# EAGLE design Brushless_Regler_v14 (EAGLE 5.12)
BENENNUNG: BL-Regler v14; DATUM: 27.01.2012; PROJEKT: Quadrokopter v1; SEITE: 1; ZEICHNER: Urban B.
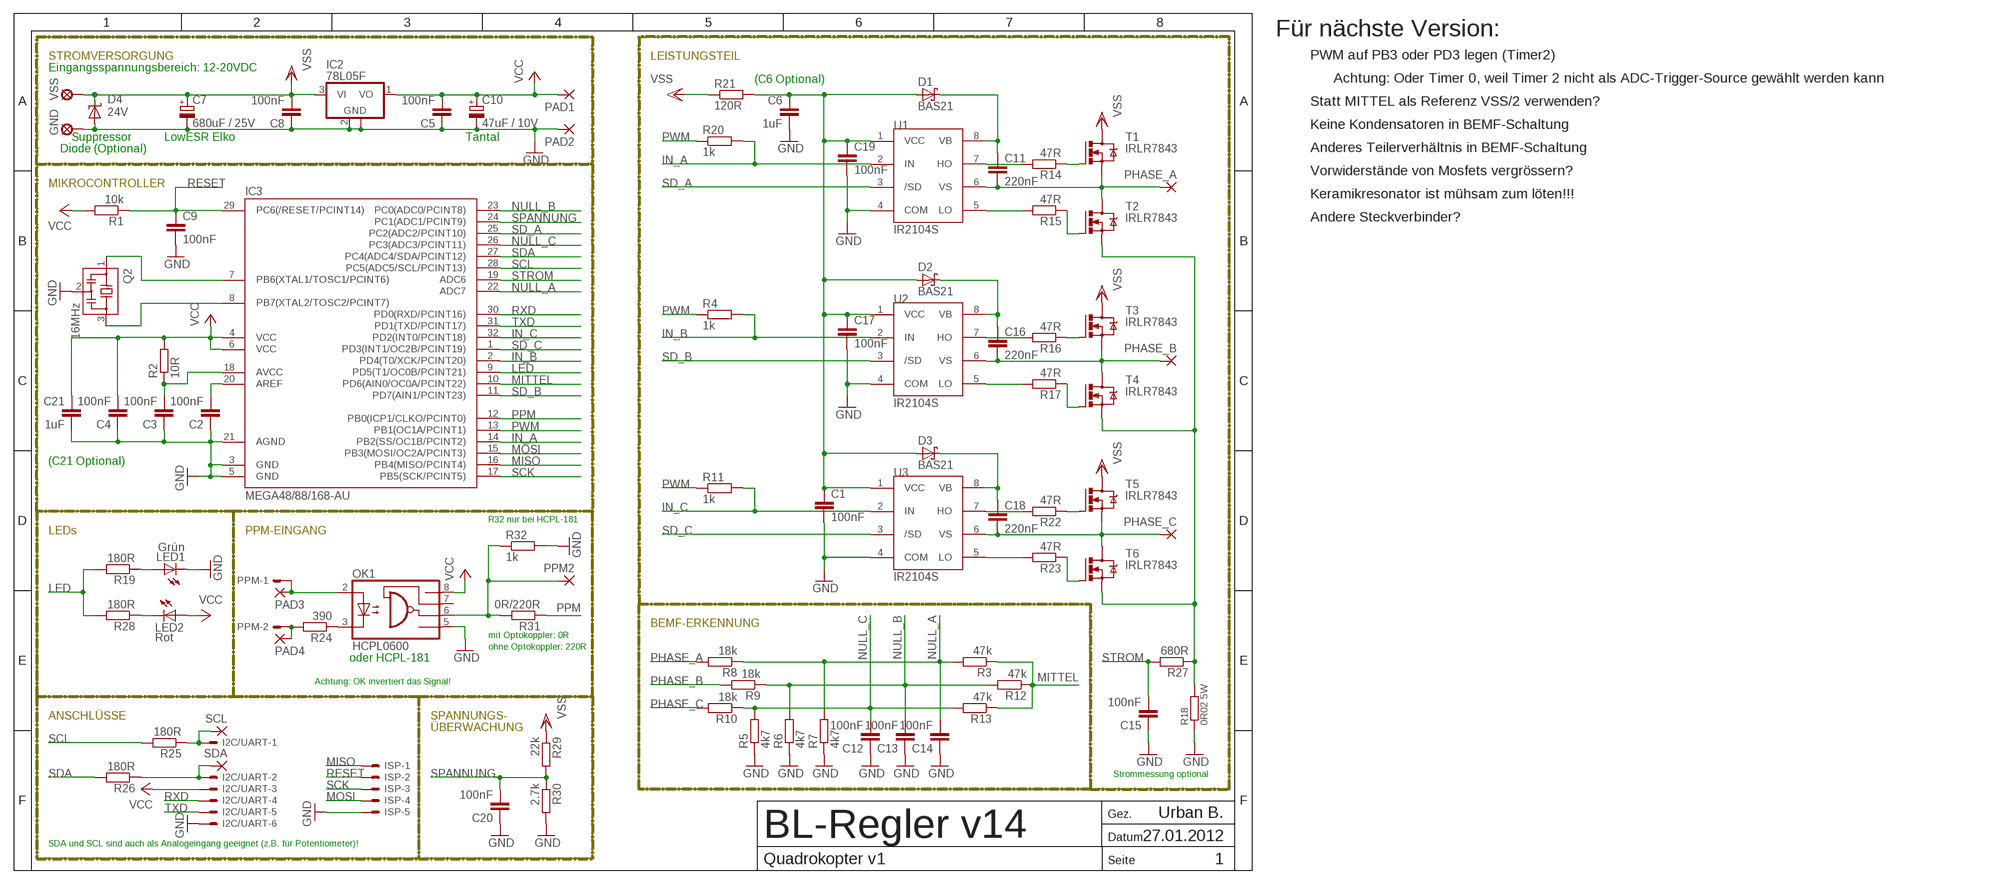
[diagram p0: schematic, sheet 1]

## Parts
C1  100nF  C-EUC0603  [C0603]
C2  100nF  C-EUC0603  [C0603]
C3  100nF  C-EUC0603  [C0603]
C4  100nF  C-EUC0603  [C0603]
C5  100nF  C-EUC0603  [C0603]
C6  1uF  C-EUC0805  [C0805]
C7  680uF / 25V  CPOL-EUE5-10.5  [E5-10,5]
C8  100nF  C-EUC0603  [C0603]
C9  100nF  C-EUC0603  [C0603]
C10  47uF / 10V  CPOL-EUB/3528-21R  [B/3528-21R]
C11  220nF  C-EUC0603  [C0603]
C12  100nF  C-EUC0603  [C0603]
C13  100nF  C-EUC0603  [C0603]
C14  100nF  C-EUC0603  [C0603]
C15  100nF  C-EUC0603  [C0603]
C16  220nF  C-EUC0603  [C0603]
C17  100nF  C-EUC0603  [C0603]
C18  220nF  C-EUC0603  [C0603]
C19  100nF  C-EUC0603  [C0603]
C20  100nF  C-EUC0603  [C0603]
C21  1uF  C-EUC0805  [C0805]
D1  BAS21  BAS40  [SOT23]
D2  BAS21  BAS40  [SOT23]
D3  BAS21  BAS40  [SOT23]
D4  24V  SUPPRESSOR-SMBJ  [SMBJ]
GND  SE14  [SE14]
I2C/UART  53261-06  [53261-06]
IC2  78L05F  [SOT89]
IC3  MEGA48/88/168-AU  [TQFP32-08]
ISP  53261-05  [53261-05]
LED1  Grün  LEDCHIP-LED0805  [CHIP-LED0805]
LED2  Rot  LEDCHIP-LED0805  [CHIP-LED0805]
OK1  HCPL0600  [SOIC08]
PAD1  SMD2  [SMD1,27-2,54]
PAD2  SMD2  [SMD1,27-2,54]
PAD3  SMD2  [SMD1,27-2,54]
PAD4  SMD2  [SMD1,27-2,54]
PHASE_A  WIREPADSMD5-1,8  [5-1,8]
PHASE_B  WIREPADSMD5-1,8  [5-1,8]
PHASE_C  WIREPADSMD5-1,8  [5-1,8]
PPM  53398-02  [53398-02]
PPM2  SMD2  [SMD1,27-2,54]
Q2  16MHz  CSTCR6M00G53Z  [CSTCR6M]
R1  10k  R-EU_R0603  [R0603]
R2  10R  R-EU_R0603  [R0603]
R3  47k  R-EU_R0603  [R0603]
R4  1k  R-EU_R0603  [R0603]
R5  4k7  R-EU_R0603  [R0603]
R6  4k7  R-EU_R0603  [R0603]
R7  4k7  R-EU_R0603  [R0603]
R8  18k  R-EU_R0603  [R0603]
R9  18k  R-EU_R0603  [R0603]
R10  18k  R-EU_R0603  [R0603]
R11  1k  R-EU_R0603  [R0603]
R12  47k  R-EU_R0603  [R0603]
R13  47k  R-EU_R0603  [R0603]
R14  47R  R-EU_R0603  [R0603]
R15  47R  R-EU_R0603  [R0603]
R16  47R  R-EU_R0603  [R0603]
R17  47R  R-EU_R0603  [R0603]
R18  0R02 5W  SMT-WAV  [SMT-WAV]
R19  180R  R-EU_R0603  [R0603]
R20  1k  R-EU_R0603  [R0603]
R21  120R  R-EU_R0603  [R0603]
R22  47R  R-EU_R0603  [R0603]
R23  47R  R-EU_R0603  [R0603]
R24  390  R-EU_R0603  [R0603]
R25  180R  R-EU_R0603  [R0603]
R26  180R  R-EU_R0603  [R0603]
R27  680R  R-EU_R0603  [R0603]
R28  180R  R-EU_R0603  [R0603]
R29  22k  R-EU_R0603  [R0603]
R30  2.7k  R-EU_R0603  [R0603]
R31  0R/220R  R-EU_R0603  [R0603]
R32  1k  R-EU_R0603  [R0603]
SCL  SMD2  [SMD1,27-2,54]
SDA  SMD2  [SMD1,27-2,54]
T1  IRLR7843  IRFR1205  [DPACK]
T2  IRLR7843  IRFR1205  [DPACK]
T3  IRLR7843  IRFR1205  [DPACK]
T4  IRLR7843  IRFR1205  [DPACK]
T5  IRLR7843  IRFR1205  [DPACK]
T6  IRLR7843  IRFR1205  [DPACK]
U1  IR2104S  IR2104NEU  [SOIC8_V2]
U2  IR2104S  IR2104NEU  [SOIC8_V2]
U3  IR2104S  IR2104NEU  [SOIC8_V2]
VSS  SE14  [SE14]

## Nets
GND: C1.2 C2.1 C3.1 C4.1 C5.1 C6.2 C7.- C8.1 C9.2 C10.- C12.1 C13.1 C14.1 C15.1 C17.2 C19.2 C20.1 C21.2 D4.A GND.MP I2C/UART.6 IC2.2(GND) IC2.2@1(GND) IC3.3(GND) IC3.5(GND) IC3.21(AGND) ISP.5 LED1.C OK1.5(GND) PAD2.1(P) Q2.2 R5.1 R6.1 R7.1 R18.2 R30.2 R32.2 U1.4(COM) U2.4(COM) U3.4(COM)
IN_A: IC3.14(PB2(SS/OC1B/PCINT2)) R20.2 U1.2(IN)
IN_B: IC3.2(PD4(T0/XCK/PCINT20)) R4.2 U2.2(IN)
IN_C: IC3.32(PD2(INT0/PCINT18)) R11.2 U3.2(IN)
LED: IC3.9(PD5(T1/OC0B/PCINT21)) R19.2 R28.2
MISO: IC3.16(PB4(MISO/PCINT4)) ISP.1
MITTEL: IC3.10(PD6(AIN0/OC0A/PCINT22)) R3.1 R12.1 R13.1
MOSI: IC3.15(PB3(MOSI/OC2A/PCINT3)) ISP.4
N$1: C2.2 IC3.20(AREF)
N$2: C3.2 IC3.18(AVCC) R2.1
N$3: IC3.8(PB7(XTAL2/TOSC2/PCINT7)) Q2.3
N$4: IC3.7(PB6(XTAL1/TOSC1/PCINT6)) Q2.1
N$5: R15.1 T2.1(G)
N$6: R14.1 T1.1(G)
N$7: R17.1 T4.1(G)
N$8: R14.2 U1.7(HO)
N$9: R16.1 T3.1(G)
N$10: R16.2 U2.7(HO)
N$11: R15.2 U1.5(LO)
N$12: R17.2 U2.5(LO)
N$13: LED1.A R19.1
N$14: LED2.C R28.1
N$15: OK1.3(C) R24.1
N$16: OK1.2(A) PAD3.1(P) PPM.1
N$19: I2C/UART.2 R26.1 SDA.1(P)
N$20: I2C/UART.1 R25.1 SCL.1(P)
N$21: R23.1 T6.1(G)
N$22: R22.1 T5.1(G)
N$23: R22.2 U3.7(HO)
N$26: R23.2 U3.5(LO)
N$30: C11.1 D1.3(C) U1.8(VB)
N$36: PAD4.1(P) PPM.2 R24.2
N$50: OK1.6(VO) PPM2.1(P) R31.2 R32.1
NULL_A: C14.2 IC3.22(ADC7) R3.2 R7.2 R8.1
NULL_B: C13.2 IC3.23(PC0(ADC0/PCINT8)) R6.2 R9.1 R12.2
NULL_C: C12.2 IC3.26(PC3(ADC3/PCINT11)) R5.2 R10.1 R13.2
PHASE_A: C11.2 PHASE_A.1(P) R8.2 T1.3(S) T2.2(D) U1.6(VS)
PHASE_B: C16.2 PHASE_B.1(P) R9.2 T3.3(S) T4.2(D) U2.6(VS)
PHASE_C: C18.2 PHASE_C.1(P) R10.2 T5.3(S) T6.2(D) U3.6(VS)
PPM: IC3.12(PB0(ICP1/CLKO/PCINT0)) R31.1
PWM: IC3.13(PB1(OC1A/PCINT1)) R4.1 R11.1 R20.1
RESET: C9.1 IC3.29(PC6(/RESET/PCINT14)) ISP.2 R1.1
RXD: I2C/UART.4 IC3.30(PD0(RXD/PCINT16))
SCK: IC3.17(PB5(SCK/PCINT5)) ISP.3
SCL: IC3.28(PC5(ADC5/SCL/PCINT13)) R25.2
SD_A: IC3.25(PC2(ADC2/PCINT10)) U1.3(/SD)
SD_B: IC3.11(PD7(AIN1/PCINT23)) U2.3(/SD)
SD_C: IC3.1(PD3(INT1/OC2B/PCINT19)) U3.3(/SD)
SDA: IC3.27(PC4(ADC4/SDA/PCINT12)) R26.2
SENSE: R18.1 R27.1 T2.3(S) T4.3(S) T6.3(S)
SPANNUNG: C20.2 IC3.24(PC1(ADC1/PCINT9)) R29.2 R30.1
STROM: C15.2 IC3.19(ADC6) R27.2
TXD: I2C/UART.5 IC3.31(PD1(TXD/PCINT17))
VBB: C16.1 D2.3(C) U2.8(VB)
VBC: C18.1 D3.3(C) U3.8(VB)
VCC: C4.2 C5.2 C10.+ C21.1 I2C/UART.3 IC2.1(VO) IC3.4(VCC) IC3.6(VCC) LED2.A OK1.8(VCC) PAD1.1(P) R1.2 R2.2
VSS: C7.+ C8.2 D4.C IC2.3(VI) R21.1 R29.1 T1.2(D) T3.2(D) T5.2(D) VSS.MP
VSS2: C1.1 C6.1 C17.1 C19.1 D1.1(A) D2.1(A) D3.1(A) R21.2 U1.1(VCC) U2.1(VCC) U3.1(VCC)
Unconnected: OK1.7(VE)

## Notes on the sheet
- Für nächste Version:
- STROMVERSORGUNG | LEISTUNGSTEIL | PWM auf PB3 oder PD3 legen (Timer2)
- Eingangsspannungsbereich: 12-20VDC
- (C6 Optional) | Achtung: Oder Timer 0, weil Timer 2 nicht als ADC-Trigger-Source gewählt werden kann
- Statt MITTEL als Referenz VSS/2 verwenden?
- Keine Kondensatoren in BEMF-Schaltung
- Suppressor | LowESR Elko | Tantal
- Diode (Optional) | Anderes Teilerverhältnis in BEMF-Schaltung
- Vorwiderstände von Mosfets vergrössern?
- MIKROCONTROLLER
- Keramikresonator ist mühsam zum löten!!!
- Andere Steckverbinder?
- (C21 Optional)
- R32 nur bei HCPL-181
- LEDs | PPM-EINGANG
- BEMF-ERKENNUNG
- mit Optokoppler: 0R
- ohne Optokoppler: 220R
- oder HCPL-181
- Achtung: OK invertiert das Signal!
- ANSCHLÜSSE | SPANNUNGS-
- ÜBERWACHUNG
- Strommessung optional
- SDA und SCL sind auch als Analogeingang geeignet (z.B. für Potentiometer)!

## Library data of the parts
C1-C6 C8 C9 C11-C21 = resistor:C-EU: CAPACITOR, European symbol
C7 C10 = resistor:CPOL-EU: POLARIZED CAPACITOR, European symbol
D1-D3 = diode:BAS40: Silicon Schottky Diodes
D4 = diode:SUPPRESSOR-: Suppressor diode
GND VSS = solpad:SE14: SOLDER PAD
I2C/UART = con-molex:53?-06: CONNECTOR wire to board 1.25 mm (.049 inch) pitch header
IC2 = linear:78L*: POSITOIV-VOLTAGE REGULATORS Output up to 100 mA Source: http://focus.ti.com/lit/ds/symlink/ua78l05.pdf
IC3 = avr-6:MEGA48/88/168
ISP = con-molex:53?-05: CONNECTOR wire to board 1.25 mm (.049 inch) pitch header
LED1 LED2 = led:LED: LED
OK1 = optocoupler:HCPL0600: HEWLETT PACKARD OPTO COUPLER
PAD1-PAD4 PPM2 SCL SDA = wirepad:SMD2: SMD PAD
PHASE_A PHASE_B PHASE_C = wirepad:WIREPAD: Wire PAD connect wire on PCB
PPM = con-molex:53?-02: CONNECTOR
Q2 = murata-filter:CSTCR: Resonator Source: murata.co.jp
R1-R17 R19-R32 = resistor:R-EU_: RESISTOR, European symbol
R18 = isabellen:SMT-WAV
T1-T6 = irf-3:IRFR1205
U1-U3 = 0_ICs:IR2104

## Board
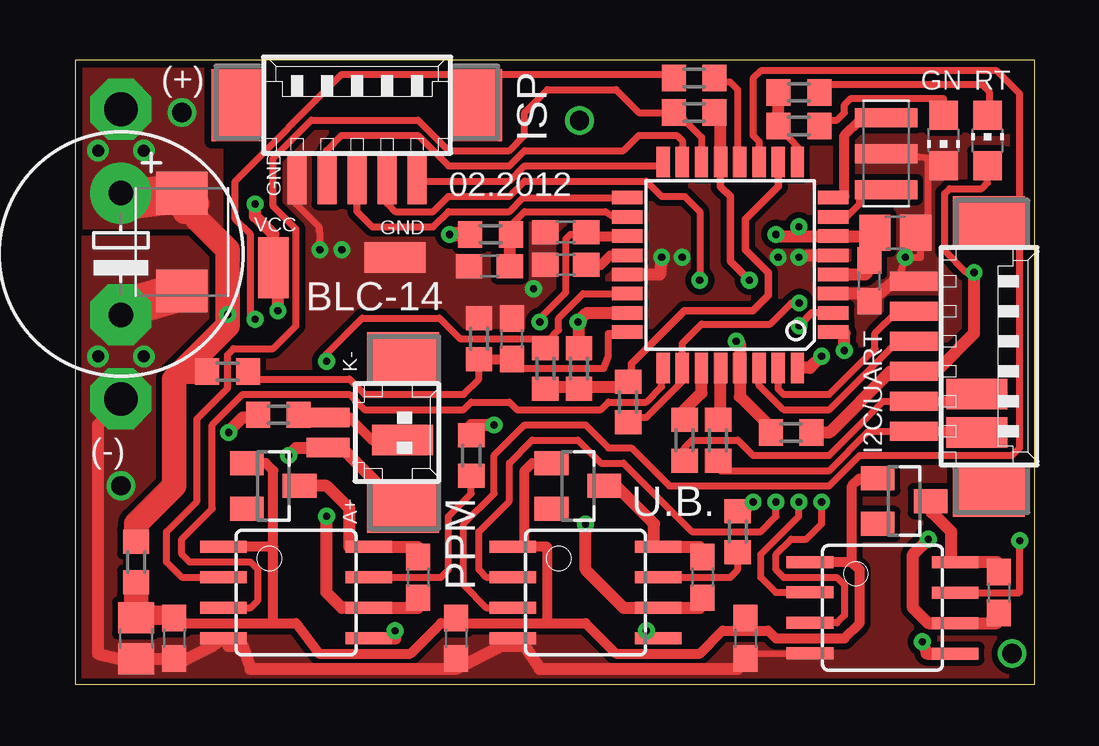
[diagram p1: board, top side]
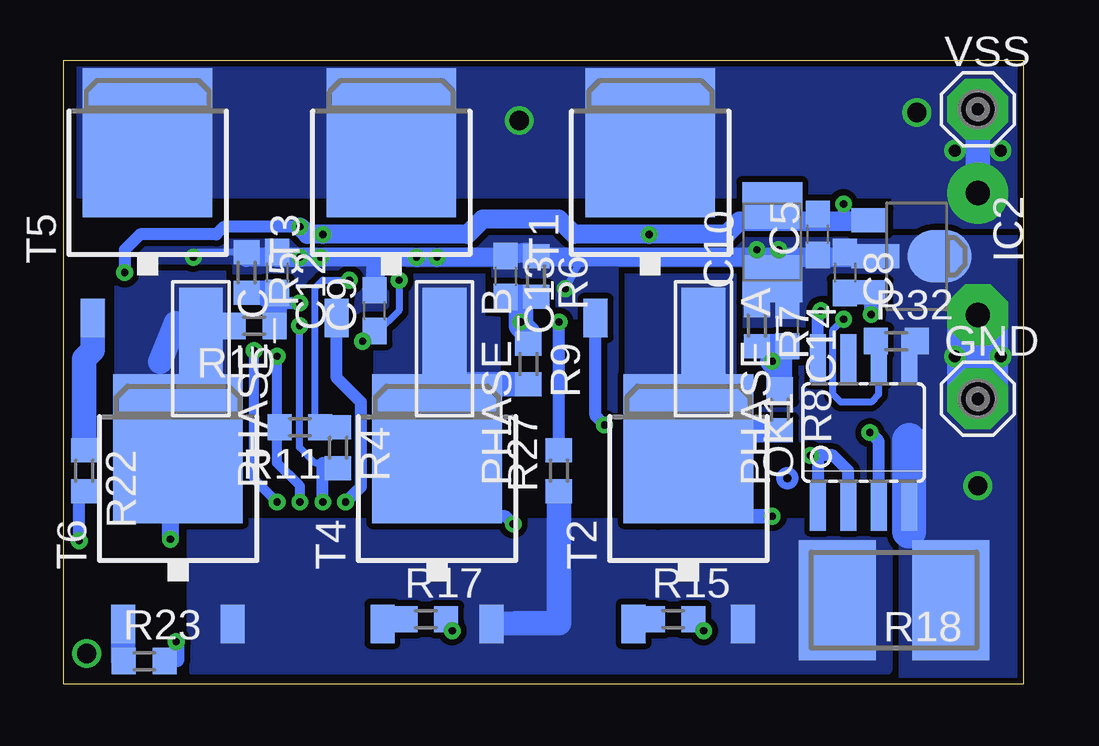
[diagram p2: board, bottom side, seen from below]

Size 40 x 26 mm. Coordinates in mm from the lower left corner, seen from the top.
Outline: 0,0 40,0 40,26 0,26 0,0
Copper layers (1*16): Top 0.035mm / dielectric 1.5mm / Bottom 0.035mm
Design rules "platinensammler_02": minimum track width 0.15mm, minimum drill 0.3mm, track to track 0.15mm, track to pad 0.15mm, pad to pad 0.15mm, via to via 0.15mm, smd to smd 0mil, copper to edge 0.2mm, drill to drill 0.2mm, minimum pad ring 0.2mm, minimum via ring 0.2mm, stop-mask expansion 4mil, vias tented up to drill 0.8mm, thermal gap 0.15mm

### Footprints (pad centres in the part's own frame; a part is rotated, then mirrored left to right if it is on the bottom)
C0603 = smd 1.1 x 1: 1 -0.85,0; 2 0.85,0
C0805 = smd 1.3 x 1.5: 1 -0.85,0; 2 0.85,0
E5-10,5 = drill 1.016 pad 2.54 round: + -2.54,0 | drill 1.016 pad 2.54 octagon: - 2.54,0
B/3528-21R = smd 1.95 x 2.5: + 1.525,0; - -1.525,0
SOT23 = smd 1 x 1.4: 1 -0.95,-1.1; 2 0.95,-1.1; 3 0,1.1
SMBJ = smd 1.78 x 2.16: A 2.04,0; C -2.03,0
SE14 = drill 1.397 pad 2.54 octagon: MP 0,0
53261-06 = smd 0.8 x 2: 1 3.125,-2.5; 2 1.875,-2.5; 3 0.625,-2.5; 4 -0.625,-2.5; 5 -1.875,-2.5; 6 -3.125,-2.5 | smd 2.1 x 3: S1 5.625,0.625; S2 -5.625,0.625
SOT89 = smd 1 x 1.5: 1 -1.499,-1.981; 3 1.499,-1.981 | smd 1 x 2: 2 0,-1.727 | smd 2.2 x 2.684: 2@1 0,0.94
TQFP32-08 = smd 1.27 x 0.559: 1 -4.293,2.8; 2 -4.293,2; 3 -4.293,1.2; 4 -4.293,0.4; 5 -4.293,-0.4; 6 -4.293,-1.2; 7 -4.293,-2; 8 -4.293,-2.8; 17 4.293,-2.8; 18 4.293,-2; 19 4.293,-1.2; 20 4.293,-0.4; 21 4.293,0.4; 22 4.293,1.2; 23 4.293,2; 24 4.293,2.8 | smd 0.559 x 1.27: 9 -2.8,-4.293; 10 -2,-4.293; 11 -1.2,-4.293; 12 -0.4,-4.293; 13 0.4,-4.293; 14 1.2,-4.293; 15 2,-4.293; 16 2.8,-4.293; 25 2.8,4.293; 26 2,4.293; 27 1.2,4.293; 28 0.4,4.293; 29 -0.4,4.293; 30 -1.2,4.293; 31 -2,4.293; 32 -2.8,4.293
53261-05 = smd 0.8 x 2: 1 2.5,-2.5; 2 1.25,-2.5; 3 0,-2.5; 4 -1.25,-2.5; 5 -2.5,-2.5 | smd 2.1 x 3: S1 5,0.625; S2 -5,0.625
CHIP-LED0805 = smd 1.2 x 1.2: A 0,-1.05; C 0,1.05
SOIC08 = smd 0.66 x 2.032: 1 -1.905,-3.073; 2 -0.635,-3.073; 3 0.635,-3.073; 4 1.905,-3.073; 5 1.905,3.073; 6 0.635,3.073; 7 -0.635,3.073; 8 -1.905,3.073
SMD1,27-2,54 = smd 1.27 x 2.54: 1 0,0
5-1,8 = smd 1.829 x 5.08: 1 0,0
53398-02 = smd 0.8 x 1.8: 1 0.625,-2.5; 2 -0.625,-2.5 | smd 2.1 x 3: S1 3.125,0.625; S2 -3.125,0.625
CSTCR6M = smd 0.8 x 2.6: 1 -1.5,0; 2 0,0; 3 1.5,0
R0603 = smd 1 x 1.1: 1 -0.85,0; 2 0.85,0
SMT-WAV = smd 3.2 x 5: 1 2.362,0; 2 -2.362,0
DPACK = smd 1 x 1.6: 1 -2.28,-4.8; 3 2.28,-4.8 | smd 5.4 x 6.2: 2 0,2.5
SOIC8_V2 = smd 0.5 x 1.946: 1 -1.905,-3.027; 2 -0.645,-3.027; 3 0.625,-3.027; 4 1.895,-3.027; 5 1.905,3.027; 6 0.635,3.027; 7 -0.635,3.027; 8 -1.905,3.027

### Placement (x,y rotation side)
C1  27.94,1.91 270 top
C2  20.45,17.46 0 top
C3  17.27,17.41 0 top
C4  33.1,16.8 90 top
C5  8.57,18.73 90 bottom
C6  2.54,1.91 270 top
C7  1.91,17.92 270 top
C8  7.45,17.14 270 bottom
C9  27.05,15.56 90 bottom
C10  10.48,18.41 90 bottom
C11  14.29,4.45 270 top
C12  31.11,17.14 270 bottom
C13  21.59,16.98 270 bottom
C14  9.84,14.92 270 bottom
C15  20.45,18.83 0 top
C16  26.15,4.45 270 top
C17  15.88,1.91 270 top
C18  38.5,3.81 270 top
C19  4.13,1.91 270 top
C20  18.2,14.39 270 top
C21  34.18,18.8 0 top
D1  8.26,8.26 270 top
D2  20.95,8.26 270 top
D3  34.55,7.62 270 top
D4  4.45,18.41 270 top
GND  1.91,11.88 0 bottom
I2C/UART  37.47,13.65 270 top
IC2  4.45,17.82 270 bottom
IC3  27.3,17.46 180 top
ISP  11.75,23.5 0 top
LED1  36.2,22.65 180 top
LED2  38.03,22.65 0 top
OK1  6.67,10.48 0 bottom
PAD1  8.26,17.35 0 top
PAD2  13.34,17.78 90 top
PAD3  13.65,7.3 90 top
PAD4  13.65,10.16 90 top
PHASE_A  13.34,13.97 180 bottom
PHASE_B  24.13,13.97 180 bottom
PHASE_C  34.29,13.97 180 bottom
PPM  13.04,10.48 270 top
PPM2  16.83,24.13 0 top
Q2  33.8,22.1 90 top
R1  29.84,10.48 0 top
R2  17.32,18.73 180 top
R3  19.6,13.15 90 top
R4  28.57,9.84 270 bottom
R5  32.38,17.14 270 bottom
R6  20.32,16.98 270 bottom
R7  11.11,14.92 270 bottom
R8  10.16,11.43 270 bottom
R9  20.64,13.34 270 bottom
R10  32.07,14.92 180 bottom
R11  30.16,10.7 180 bottom
R12  21,13.15 90 top
R13  23.05,11.75 270 top
R14  16.51,9.53 270 top
R15  14.61,2.7 0 bottom
R16  27.62,6.35 270 top
R17  24.91,2.7 0 bottom
R18  5.4,3.49 180 bottom
R19  30.16,23.25 180 top
R20  25.8,23.81 180 top
R21  2.54,5.08 270 top
R22  39.15,8.89 270 bottom
R23  36.65,0.95 0 bottom
R24  8.47,11.22 0 top
R25  26.8,10.16 90 top
R26  25.4,10.16 90 top
R27  19.37,8.89 90 bottom
R28  30.16,24.65 180 top
R29  6.35,13.02 0 top
R30  16.84,14.39 90 top
R31  25.8,25.25 180 top
R32  5.3,14.29 0 bottom
SCL  37.58,10.48 90 top
SDA  37.58,12.08 90 top
T1  15.56,20.05 0 bottom
T2  13.97,7.3 0 bottom
T3  26.35,20.05 0 bottom
T4  24.45,7.3 0 bottom
T5  36.51,20.05 0 bottom
T6  35.24,7.3 0 bottom
U1  9.21,3.81 270 top
U2  21.27,3.81 270 top
U3  33.66,3.17 270 top
VSS  1.91,23.95 0 bottom

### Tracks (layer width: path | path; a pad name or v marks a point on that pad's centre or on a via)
GND  (via drill 0.3, 0.5, 0.8)
  Top 0.29: 35.56,21.91 35.88,21.91 LED1.C | I2C/UART.6 35.24,16.82 35.24,16.83 | v10.2,18.1 10.16,19.05 9.21,20 9.21,20.32 | 36.2,21.27 36.41,21.49 | 35.56,21.91 35.88,21.18 LED1.C | 35.56,21.91 Q2.2 | 35.56,21.91 35.56,19.37 35.24,19.05 35.24,17.78 v34.61,17.78 34.29,16.83
  Top 0.3: 28.26,1.27 30.17,1.28 | 15.88,0.64 C17.2 | 27.62,0.64 C1.2 | U2.4 17.78,1.6 17.78,1.59 | 9.21,20.32 9.25,20.36 | LED1.C 36.41,21.49
  Top 0.5: 30.17,1.28 U3.4 | 28.26,1.27 27.62,0.64 19.37,0.64 18.73,1.59 17.78,1.59 15.88,0.64 7.3,0.64 6.99,1.59 6.38,1.59 U1.4 5.72,1.6 4.45,0.95 3.91,0.95 C19.2 C6.2 1.8,1.05 0.95,1.27 0.95,10.79 1.91,11.75 | IC3.21 24.36,17.06 v24.45,17.78 | 9.25,20.36 ISP.5 | IC3.5 30.56,17.86 v30.16,17.78 | LED1.C 36.2,21.27 | I2C/UART.6 34.91,16.83 34.29,16.83 34.19,16.83 C4.1 33.02,16.26 IC3.3
  Top 1.016: 1.91,11.75 GND.MP
  Top 1.676: D4.A 2.27,15.74 C7.-
  Bottom 0.29: R5.1 34.39,18 v34.61,17.78
  Bottom 0.3: 18.41,17.78 v19.1,16.46
  Bottom 0.5: 7.3,17.78 C8.1 | 8.57,17.78 C5.1 | C14.1 9.53,16.41 9.53,17.78 | 10.48,17.78 C10.-
  Bottom 0.8: C10.- 11.11,17.52 | 26.99,17.78 v29.3,17.78 v30.16,17.78 | 31.11,17.78 32.07,17.78 32.38,17.78 | 26.99,17.78 C9.2 | 26.99,17.78 v25.3,17.78 v24.45,17.78 21.91,17.78 | 10.48,17.78 18.41,17.78 20.32,17.78 | 20.75,18 C13.1
  Bottom 0.813: IC2.2 7.3,17.78 8.57,17.78 9.53,17.78 10.48,17.78 | v30.16,17.78 31.11,17.78 C12.1 | R5.1 32.28,18 32.07,17.78 | 20.32,17.78 R6.1 20.75,18 | C13.1 21.91,17.78
  Bottom 1.016: 11.11,17.52 R7.1
  Bottom 1.422: 4.76,6.35 4.76,10.16
  Bottom 2.54: GND.MP C7.-
  other vias: 2.86,13.65 0.95,13.65 1.91,8.26 11.11,18.1
  pour Top (isolate 0.254, rank 2, no thermals): 0.32,0.32 39.69,0.32 39.69,25.72 0.32,25.72
  pour Bottom (isolate 0.254, rank 6, no thermals): 39.69,0.32 0.32,0.32 0.32,25.72 39.69,25.72
IN_A
  Top 0.29: U1.2 4.43,4.46 3.81,5.08 3.81,6.35 5.08,7.62 5.08,11.05 6.35,12.32 6.35,13.72 6.6,13.97 8.26,13.97 9.21,14.92 9.21,18.95 8.26,19.9 8.26,21.91 9.84,23.5 14.29,23.5 15.56,22.23 18.1,22.23 18.73,22.86 18.73,23.81 19.68,24.77 22.54,24.77 23.5,23.81 R20.2 | IC3.14 26.11,22.79 25.08,23.81
  Top 0.3: R20.2 25.08,23.81
IN_B  (via drill 0.3)
  Top 0.29: U2.2 17.14,4.46 16.83,4.76 16.83,6.35 18.1,7.62 18.1,9.21 19.05,10.16 20.95,10.16 21.91,9.21 22.86,9.21 25.72,6.35 28.57,6.35 29.21,6.99 v29.21,7.58
  Top 0.305: IC3.2 30.7,15.46 v30.18,14.92
  Bottom 0.3: v30.18,14.92 30.18,9.86 29.53,9.21 29.21,9.21
  Bottom 0.5: v29.21,7.58 29.21,9.21 28.79,9.21 R4.2
IN_C  (via drill 0.3)
  Top 0.29: U3.2 29.2,3.82 28.57,4.45 28.57,5.4 30.16,6.99 v30.16,7.58
  Top 0.5: IC3.32 30.63,13.17 v31.11,13.65
  Bottom 0.3: R11.2 31.34,10.7 31.11,10.79
  Bottom 0.406: v31.11,13.65 31.11,10.79 31.11,9.21 30.16,8.26 v30.16,7.58
LED
  Top 0.3: IC3.9 30.11,22.39 R19.2
  Top 0.5: R19.2 R28.2
MISO
  Top 0.29: 24.45,21.59 18.73,21.59 18.1,20.95 14.29,20.95
  Top 0.3: IC3.16 24.5,22.17 24.45,21.59 | 14.29,20.95 14.29,20.64 ISP.1
MITTEL
  Top 0.305: IC3.10 29.3,20.73 27.94,19.37 27.94,18.1 28.89,17.14 28.89,16.19 28.26,15.56 25.4,15.56 23.18,13.34 23.18,12.72 R13.1
  Top 0.5: 19.68,12.38 19.79,12.06 R3.1 19.68,12.38 | 19.68,12.38 20.85,12.38 R12.1 21.17,12.38 22.96,12.38 R13.1
MOSI
  Top 0.29: IC3.15 25.3,22.64 25.08,22.86 23.5,22.86 22.86,22.23 18.73,22.23 18.1,21.59 15.56,21.59 14.29,22.86 11.11,22.86 10.48,22.23 10.48,21.02
  Top 0.3: ISP.4 10.48,21.02
N$1
  Top 0.406: IC3.20 22.31,17.86 21.91,17.46 C2.2
N$2
  Top 0.29: IC3.18 22.45,19.46 22.1,19.68 18.73,19.68 18.1,19.05 18.1,18.8 R2.1
  Top 0.5: C3.2 18.11,18.68 R2.1
N$3
  Top 0.406: IC3.8 32.01,20.26 32.07,20.32 32.07,22.86 32.7,23.5 33.71,23.5 Q2.3
N$4
  Top 0.29: IC3.7 32.16,19.46 32.7,20 32.7,20.64 33.76,20.64 Q2.1
N$5
  Bottom 0.5: R15.1 16.21,2.54 T2.1
N$6  (via drill 0.3)
  Top 0.5: v17.46,10.79 16.51,10.79 R14.1
  Bottom 0.5: T1.1 17.84,11.17 v17.46,10.79
N$7
  Bottom 0.5: R17.1 26.69,2.54 T4.1
N$8
  Top 0.29: U1.7 15.24,4.45 15.56,4.76 15.56,6.99 16.51,7.94 R14.2
N$9  (via drill 0.3)
  Top 0.5: R16.1 27.84,7.2 v28.26,7.58
  Bottom 0.5: T3.1 28.63,12.76 27.62,11.75 27.62,8.21 v28.26,7.58
N$10
  Top 0.29: 27.52,5.4 R16.2 27.62,4.76 27.3,4.45 U2.7
N$11  (via drill 0.3)
  Top 0.5: v13.34,2.22 13.34,1.91 U1.5
  Bottom 0.5: R15.2 13.65,2.54 v13.34,2.22
N$12  (via drill 0.3)
  Top 0.5: v23.81,2.22 23.81,1.91 U2.5
  Bottom 0.5: R17.2 23.81,2.54 v23.81,2.22
N$13
  Top 0.3: LED1.A 36.2,24.4 32.34,24.4 32.07,24.13 32.07,23.81 31.75,23.5 31.26,23.5 R19.1
N$14
  Top 0.3: R28.1 31.01,24.66 31.11,25 37.78,25 38.1,24.68 38.1,23.98 LED2.C
N$15  (via drill 0.3)
  Top 0.5: v6.4,10.48 6.4,10.53 6.99,11.11 7.51,11.11 R24.1
  Bottom 0.406: OK1.3 6.04,7.4
  Bottom 0.5: OK1.3 6.03,10.11 v6.4,10.48
N$16  (via drill 0.3)
  Top 0.5: v8.89,9.53 9.21,9.84 PPM.1 11.1,9.85 PAD3.1
  Bottom 0.5: 8.57,9.53 7.94,9.53 7.3,8.89 OK1.2 | 8.57,9.53 v8.89,9.53 | 8.57,9.53 8.57,7.62
N$17  (via drill 0.8)
  other vias: 39.05,1.27
N$19
  Top 0.29: I2C/UART.2 33.69,11.78 31.43,9.53 28.26,9.53 27.62,10.16 25.72,10.16 25.4,9.84 R26.1
  Top 0.406: I2C/UART.2 36.86,11.78 37.15,12.06 SDA.1
N$20
  Top 0.29: I2C/UART.1 33.07,10.53 31.43,8.89 26.89,8.89 R25.1
  Top 0.406: I2C/UART.1 37.52,10.53 SCL.1
N$21
  Bottom 1.016: T6.1 37.52,0.97 R23.1
N$22
  Bottom 1.016: R22.1 39.15,13.55 38.79,13.91 T5.1
N$23  (via drill 0.3)
  Top 0.29: U3.7 39.37,3.81 v39.37,5.97
  Bottom 0.5: R22.2 39.37,8.04 v39.37,5.97
N$26  (via drill 0.3)
  Top 0.5: U3.5 35.49,1.27 v35.32,1.76
  Bottom 0.5: R23.2 35.24,0.95 35.24,1.69 v35.32,1.76
N$30
  Top 0.5: C11.1 14.29,5.71 U1.8 11.43,5.71 11.43,7.3 10.48,8.26 D1.3
N$36
  Top 0.406: PPM.2 11.44,11.1 12.38,10.16 PAD4.1
  Top 0.5: 9.53,11.11 R24.2 9.21,11.11 9.53,11.11 | 9.53,11.11 10.53,11.11 PPM.2
N$50  (via drill 0.3)
  Top 0.254: PPM2.1 16.83,25.08 17.14,25.4
  Top 0.29: R31.2 24.8,25.4 17.14,25.4 11.11,25.4 6.67,20.95 6.67,19.37 7.3,18.73 7.3,15.4 v7.5,15.2
  Bottom 0.29: OK1.6 6.03,12.06 6.35,11.75 7.62,11.75 7.94,12.06 7.94,14.76 v7.5,15.2
  Bottom 0.406: R32.1 6.03,14.07 OK1.6
NULL_A  (via drill 0.3)
  Top 0.29: R3.2 19.68,14.29 20.15,14.75 20.15,15.24 21.17,16.26 IC3.22
  Top 0.3: v10.48,13.45 10.48,13.76 11.96,15.24 15.18,15.24 16.04,14.39 19.85,14.39 R3.2
  Bottom 1.017: C14.2 10.16,14.07 | 10.16,13.34 R8.1 | 10.16,14.07 R7.2 | 10.16,13.34 v10.48,13.45 | 10.16,14.07 10.16,13.34
NULL_B  (via drill 0.3)
  Top 0.3: IC3.23 23.08,15.46
  Top 0.5: IC3.23 21.34,15.46 v20.95,15.08 21,15.04 R12.2
  Bottom 1.016: 20.95,16.13 R6.2 | 20.95,16.13 C13.2 | 20.95,16.13 v20.95,15.08 20.95,14.92 20.64,14.61 R9.1
NULL_C  (via drill 0.3)
  Top 0.29: v30.18,15.88 29.84,15.88 28.97,15 26.11,15 25.3,14.19 IC3.26 25.3,12.61 23.81,11.11 23.39,11.11 R13.2
  Bottom 0.5: v30.18,15.88 31.01,15.88 C12.2
  Bottom 1.017: C12.2 31.75,16.3 | 31.75,16.3 R5.2 | R10.1 31.22,16.08 31.75,16.3
PHASE_A  (via drill 0.3)
  Top 0.5: v10.48,6.99 10.48,3.81 11.11,3.17 U1.6 14.29,3.17 C11.2
  Bottom 0.5: 15.24,7.62 T2.2
  Bottom 0.61: v10.48,6.99 15.24,6.99 15.24,7.62
  Bottom 1.017: R8.2 14.14,10.58 T2.2
  pour Bottom (isolate 0.254, no thermals): 12.06,17.14 12.06,11.43 16.51,11.43 16.51,17.14
PHASE_B  (via drill 0.3)
  Top 0.5: v21.27,6.67 21.27,4.76 22.86,3.17 U2.6 26.04,3.17 C16.2
  Bottom 0.5: T4.2 24.49,6.99 21.59,6.99 v21.27,6.67
  Bottom 1.016: R9.2 24.55,12.48
  pour Bottom (isolate 0.254, no thermals): 25.4,17.14 22.54,17.14 22.54,15.24 21.91,15.24 21.91,11.43 26.99,11.43 26.99,13.97 26.35,13.97 26.35,15.56 25.4,16.51
PHASE_C  (via drill 0.3)
  Top 0.5: C18.2 38.42,2.54 U3.6 35.56,2.54 34.92,3.17 34.92,5.4 v35.56,6.03
  Bottom 0.5: 35.56,7.9 T6.2
  Bottom 0.7: v35.56,6.03 35.56,7.9
  Bottom 1.016: R10.2 35.34,15.03 35.98,13.44
  pour Bottom (isolate 0.254, no thermals): 33.34,17.14 33.34,11.43 37.78,11.43 37.78,17.14
PPM
  Top 0.29: IC3.12 27.62,21.75 27.62,24.77 27.3,25.08 26.82,25.08 R31.1
PWM  (via drill 0.3)
  Top 0.305: IC3.13 26.91,20.72 27.3,20.32 27.3,17.62 v28.1,16.83
  Top 0.5: IC3.13 26.91,23.48 R20.1
  Bottom 0.3: v28.1,16.83 29.21,16.83 29.53,16.51 29.53,10.91 R11.1 R4.1
RESET  (via drill 0.3)
  Top 0.29: 13.02,20.66 13.02,20 13.34,19.68 14.92,19.68 15.56,20.32 18.1,20.32 18.73,20.95 23.81,20.95 24.45,20.32 25.4,20.32 26.04,19.68 v26.04,16.83
  Top 0.3: 13.02,20.66 ISP.2
  Top 0.5: R1.1 28.89,10.79 27.7,11.98 IC3.29 27.7,14.21 v27.55,14.29
  Bottom 0.3: v27.55,14.29 C9.1 26.99,14.61 26.04,15.56 v26.04,16.83
RXD
  Top 0.29: IC3.30 28.5,12.45 29.53,11.43 31.43,11.43 33.97,13.97 34.29,14.27 34.3,14.28 | 34.95,14.29 I2C/UART.4 34.3,14.28 | 34.3,14.28 34.29,14.29
SCK
  Top 0.29: ISP.3 11.75,19.68 12.38,19.05 14.92,19.05 15.56,19.68 18.1,19.68 18.68,20.26 IC3.17
SCL
  Top 0.5: IC3.28 26.91,10.88 26.67,10.79 R25.2
SD_A
  Top 0.29: 6.19,3.17 7.3,3.17 7.62,3.49 7.62,4.76 7.3,5.08 4.76,5.08 4.45,5.4 4.45,6.03 5.71,7.3 5.71,10.79 6.99,12.06 11.43,12.06 12.06,11.43 16.19,11.43 16.51,11.75 18.1,11.75 18.41,11.43 21.91,11.43 22.23,11.75 23.81,11.75 24.45,12.38 24.45,13.11 IC3.25
  Top 0.5: U1.3 6.19,3.17
SD_B
  Top 0.29: U2.3 17.14,3.19 16.19,4.13 16.19,6.67 17.46,7.94 17.46,9.53 18.73,10.79 21.27,10.79 22.23,9.84 23.18,9.84 24.77,8.26 31.43,8.26 32.7,9.53 39.05,9.53 39.37,9.84 39.37,24.6 38.42,25.55 28.57,25.55 28.26,25.23 28.26,22.86 28.5,22.61 IC3.11
SD_C  (via drill 0.3)
  Top 0.29: U3.3 31.76,2.55 32.07,2.86 32.07,4.13 31.75,4.45 29.53,4.45 29.21,4.76 29.21,5.4 29.84,6.03 30.48,6.03 31.11,6.67 v31.11,7.58
  Top 0.3: IC3.1 31.17,14.66 | 32.07,14.61 32.01,14.66
  Top 0.5: 32.01,14.66 IC3.1 | v32.07,13.9 32.07,14.61
  Bottom 0.406: v32.07,13.9 32.07,8.53 v31.11,7.58
SDA
  Top 0.5: IC3.27 26.11,12.13 25.4,11.43 R26.2
SENSE
  Bottom 1.016: R27.1 19.37,2.54 21.18,2.54 T4.3
  pour Bottom (isolate 0.254, no thermals): 5.71,0.64 34.61,0.64 34.61,6.67 5.71,6.67
SPANNUNG
  Top 0.29: R30.1 16.83,13.53 16.83,12.7 16.19,12.06 12.06,12.06 11.43,12.7 7.52,12.7 R29.2
  Top 0.3: C20.2 18.31,13.15 22.04,13.15 22.23,13.65 22.23,14.61 22.95,14.61 IC3.24
  Top 0.406: R30.1 C20.2
STROM  (via drill 0.3)
  Top 0.29: v19.37,15.08 19.37,15.24 20.45,16.32 20.45,18.55 20.64,18.73 20.95,18.73
  Top 0.406: IC3.19 21.47,18.66 C15.2
  Top 0.5: 20.95,18.73 21.2,18.73 C15.2
  Bottom 0.5: R27.2 v19.37,15.08
TXD
  Top 0.29: IC3.31 29.3,12.29 29.53,12.06 31.43,12.06 33.34,13.97 33.34,14.61 34.29,15.56 34.94,15.56
  Top 0.3: 34.94,15.56 I2C/UART.5
VBB
  Top 0.5: C16.1 26.04,5.71 U2.8 24.13,5.71 24.13,6.67 22.54,8.26 D2.3
VBC
  Top 0.5: C18.1 38.42,5.08 U3.8 36.51,5.25 36.51,6.35 35.71,7.16 D3.3
VCC  (via drill 0.3)
  Top 0.29: 38,21.49 LED2.A 38.03,20.88 37.78,20.64 36.45,20.64 36.25,20.44 36.25,18.04 37.15,17.14 v37.47,17.14 | 8.45,16.7 8.57,16.83
  Top 0.3: 31.18,18.66 IC3.6 | 8.57,16.83 PAD1.1
  Top 0.5: R1.2 31.43,10.48 33.98,13.03 I2C/UART.3 35.89,13.03 37.47,14.61 v37.47,17.14 | 31.18,18.66 29.28,18.66 v29.21,18.73 | v30.16,19.05 30.16,18.73 | PAD1.1 8.26,18.73 7.5,19.49 v7.5,20 | IC3.4 32.94,17.06 33.02,17.14 C4.2 33.02,18.66 | IC3.6 33.02,18.66 | 33.02,18.66 33.44,18.66 C21.1 | v8.45,15.56 8.45,16.7 | R2.2 16.46,18.78
  Top 0.61: v15.6,18.73 R2.2
  Bottom 0.5: v30.16,19.05 33.34,19.05 33.66,18.73 36.83,18.73 37.47,18.1 v37.47,17.14 | 10.48,19.28 C10.+ | 8.57,19.28 C5.2 | v7.5,20 7.5,19.48 7.3,19.28 | v8.45,15.56 8.57,15.44 OK1.8
  Bottom 0.8: 11.84,19.28 12.38,18.73 v15.6,18.73 18.73,18.73 19.37,19.37 22.54,19.37 23.18,18.73 v29.21,18.73 29.84,18.73 v30.16,19.05
  Bottom 0.813: IC2.1 7.3,19.28 8.57,19.28 10.48,19.28 11.84,19.28
VSS  (via drill 0.3, 0.5, 0.8)
  Top 1.016: R21.1 2.54,6.67 4.13,8.26 4.13,12.7 4.45,13.02 | D4.C 4.57,19.68 4.76,19.68 5.08,20 4.76,20 5.08,19.37 6.35,18.1 v6.35,15.4 6.35,14.92 4.45,13.02 | 4.45,13.02 R29.1
  Top 1.676: D4.C 1.92,20.13 C7.+
  Bottom 0.61: v6.35,15.4 6.35,16.04
  Bottom 0.813: IC2.3 6.43,16.27 | C8.2 6.76,16.3 IC2.3 | 6.35,16.04 IC2.3
  Bottom 1.016: C7.+ VSS.MP
  other vias: 0.95,22.23 2.86,22.23 4.45,23.81 21.02,23.48
  pour Bottom (isolate 0.254, rank 2, no thermals): 39.37,25.72 0.32,25.72 0.32,19.05 5.4,19.05 5.4,20.32 39.37,20.32
  pour Top (isolate 0.305, no thermals): 0.32,25.72 6.03,25.72 6.03,19.05 0.32,19.05
VSS2
  Top 0.3: C17.1 15.88,2.54
  Top 0.406: D3.1 32.7,8.57 32.38,8.26 32.38,5.08 | 32.38,5.08 32.7,4.76 32.7,2.54 32.07,1.91 29.21,1.91 28.89,2.22 27.94,2.22 | 32.38,5.08 U3.1 | 8.26,5.71 U1.1 | 8.26,2.54 8.26,5.71 | 15.88,2.54 19.68,2.54 | D1.1 7.94,9.21 8.26,8.89 8.26,5.71 | 8.26,2.54 4.34,2.54 C19.1 | 19.68,2.54 19.68,5.71 18.9,5.71 18.73,5.88 | 28.04,2.54 C1.1 27.94,2.22 | D2.1 19.05,9.21 18.73,8.89 18.73,5.88 | U2.1 18.56,5.71 18.73,5.88 | 8.26,2.54 9.21,2.54 10.16,1.27 13.97,1.27 15.24,2.54 15.66,2.54 C17.1 | 19.68,2.54 21.27,2.54 22.54,1.27 26.04,1.27 26.99,2.22 27.94,2.22
  Top 0.5: 3.92,2.64 3.92,2.65 4.13,2.86 | C6.1 2.75,2.86
  Top 0.813: 2.75,2.86 4.13,2.86 C19.1
  Top 1.016: C6.1 R21.2
(copper drawn outside any net)
  shapes: Bottom circle x1

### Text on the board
tPlace: (+) | GN | RT | GND | 02.2012 | VCC | GND | BLC-14 | K- | (-) | A+ | U.B.
Blau: SCL | VCC | RXD | TXD | SDA | GND | MOSI | SCK | RESET | MISO | VSS | GND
